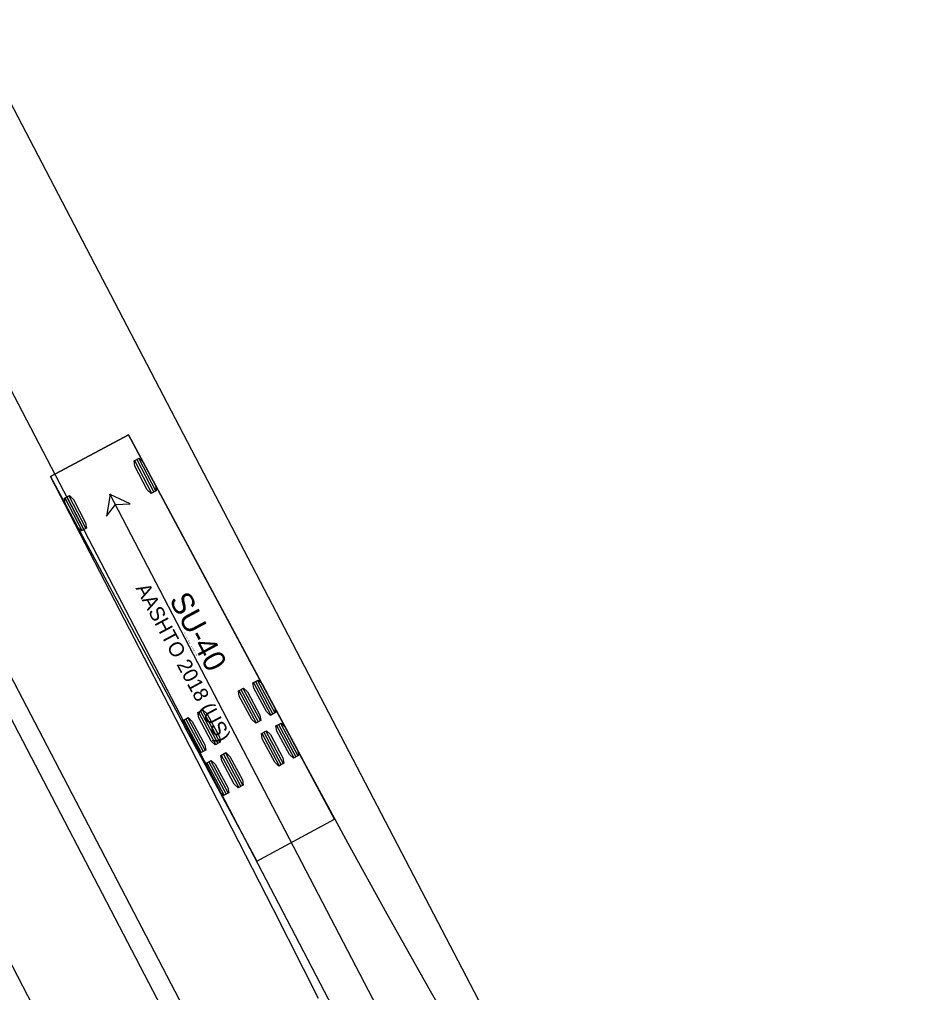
# Model space of a CAD drawing. Extents: x 2297881 to 2300600, y 559917 to 564426.
# Drawn here: x 2298908.1 to 2298989, y 562760.2 to 562848.3 of the extents above; entities that cross this region are included whole.
import ezdxf

# ---------------------------------------------------------------- set-up
doc = ezdxf.new("R2010")
doc.units = 0
for name, color, linetype in [('GE_X_Alignment', 7, 'Continuous'), ('PM_P_CL_Pass_Proh_Lt', 7, 'Continuous'), ('PM_P_Dotted_Line', 7, 'Continuous'), ('PM_P_Lane_Line', 7, 'Continuous'), ('SN_X_Public', 7, 'Continuous'), ('SV_X_Control_Cells_Found', 7, 'Continuous')]:
    doc.layers.add(name, color=color, linetype=linetype)

msp = doc.modelspace()

# ---------------------------------------------------------------- linework, layer by layer
at = {"layer": 'GE_X_Alignment'}
msp.add_line((2298386.276, 563783.359), (2299396.643, 561847.397), dxfattribs=at)
at = {"layer": 'PM_P_CL_Pass_Proh_Lt'}
msp.add_line((2298832.687, 562957.711), (2298969.176, 562696.185), dxfattribs=at)
at = {"layer": 'PM_P_Dotted_Line'}
msp.add_line((2298822.048, 562952.158), (2298958.537, 562690.633), dxfattribs=at)
at = {"layer": 'PM_P_Lane_Line'}
msp.add_line((2298843.325, 562963.263), (2299419.428, 561859.394), dxfattribs=at)
at = {"layer": 'SN_X_Public'}
for p, q in [((2298917.929, 562810.739), (2298910.88, 562806.957)), ((2298936.607, 562775.935), (2298917.929, 562810.739)), ((2298918.501, 562808.395), (2298920.042, 562805.439)), ((2298918.686, 562808.491), (2298920.226, 562805.535)), ((2298918.87, 562808.588), (2298920.411, 562805.632)), ((2298910.88, 562806.957), (2298929.558, 562772.152)), ((2298910.88, 562806.957), (2298910.88, 562806.957)), ((2298912.181, 562805.015), (2298913.722, 562802.059)), ((2298912.366, 562805.111), (2298913.907, 562802.156)), ((2298912.551, 562805.208), (2298914.092, 562802.252)), ((2298961.104, 562719.36), (2298916.296, 562805.323)), ((2298928.309, 562787.786), (2298929.885, 562784.849)), ((2298929.263, 562788.298), (2298930.839, 562785.361)), ((2298929.447, 562788.397), (2298931.023, 562785.459)), ((2298929.63, 562788.495), (2298931.207, 562785.558)), ((2298927.941, 562787.589), (2298929.518, 562784.652)), ((2298928.125, 562787.687), (2298929.701, 562784.75)), ((2298924.27, 562785.618), (2298925.846, 562782.681)), ((2298924.454, 562785.717), (2298926.03, 562782.78)), ((2298924.637, 562785.815), (2298926.213, 562782.878)), ((2298922.948, 562784.909), (2298924.525, 562781.972)), ((2298923.132, 562785.008), (2298924.708, 562782.071)), ((2298923.316, 562785.106), (2298924.892, 562782.169)), ((2298931.344, 562784.421), (2298932.92, 562781.484)), ((2298931.527, 562784.52), (2298933.104, 562781.582)), ((2298931.711, 562784.618), (2298933.287, 562781.681)), ((2298930.022, 562783.712), (2298931.598, 562780.775)), ((2298930.206, 562783.81), (2298931.782, 562780.873)), ((2298930.389, 562783.909), (2298931.965, 562780.972)), ((2298926.351, 562781.741), (2298927.927, 562778.804)), ((2298926.534, 562781.84), (2298928.11, 562778.903)), ((2298926.718, 562781.938), (2298928.294, 562779.001)), ((2298925.029, 562781.032), (2298926.605, 562778.095)), ((2298925.213, 562781.131), (2298926.789, 562778.194)), ((2298925.396, 562781.229), (2298926.972, 562778.292)), ((2298929.558, 562772.152), (2298936.607, 562775.935))]:
    msp.add_line(p, q, dxfattribs=at)
for points in [[(2298935.14, 562759.715), (2298931.065, 562767.761), (2298921.625, 562786.187), (2298910.88, 562806.957), (2298917.929, 562810.739), (2298934.006, 562780.793), (2298937.819, 562773.776), (2298941.353, 562767.365), (2298945.266, 562760.404), (2298948.756, 562754.351)], [(2298916.296, 562805.323), (2298915.95, 562803.354), (2298916.758, 562804.437), (2298918.109, 562804.479), (2298916.296, 562805.323)]]:
    msp.add_lwpolyline(points, dxfattribs=at)
for points in [[(2298918.455, 562808.371), (2298918.916, 562808.612), (2298919.271, 562808.27), (2298920.38, 562806.142), (2298920.457, 562805.656), (2298919.996, 562805.415), (2298919.641, 562805.757), (2298918.532, 562807.885)], [(2298912.135, 562804.991), (2298912.597, 562805.232), (2298912.951, 562804.89), (2298914.061, 562802.762), (2298914.137, 562802.276), (2298913.676, 562802.035), (2298913.322, 562802.377), (2298912.212, 562804.505)], [(2298916.296, 562805.323), (2298915.95, 562803.354), (2298916.758, 562804.437), (2298918.109, 562804.479)], [(2298927.896, 562787.564), (2298928.354, 562787.81), (2298928.713, 562787.473), (2298929.848, 562785.358), (2298929.93, 562784.873), (2298929.472, 562784.627), (2298929.113, 562784.964), (2298927.979, 562787.079)], [(2298929.218, 562788.274), (2298929.676, 562788.519), (2298930.035, 562788.182), (2298931.169, 562786.068), (2298931.252, 562785.582), (2298930.794, 562785.336), (2298930.435, 562785.674), (2298929.3, 562787.788)], [(2298924.225, 562785.594), (2298924.683, 562785.84), (2298925.041, 562785.503), (2298926.176, 562783.388), (2298926.259, 562782.903), (2298925.801, 562782.657), (2298925.442, 562782.994), (2298924.307, 562785.109)], [(2298922.903, 562784.885), (2298923.361, 562785.131), (2298923.72, 562784.793), (2298924.855, 562782.679), (2298924.937, 562782.193), (2298924.479, 562781.948), (2298924.12, 562782.285), (2298922.985, 562784.399)], [(2298931.298, 562784.397), (2298931.756, 562784.642), (2298932.115, 562784.305), (2298933.25, 562782.191), (2298933.333, 562781.705), (2298932.874, 562781.459), (2298932.516, 562781.797), (2298931.381, 562783.911)], [(2298929.977, 562783.687), (2298930.435, 562783.933), (2298930.793, 562783.596), (2298931.928, 562781.481), (2298932.011, 562780.996), (2298931.553, 562780.75), (2298931.194, 562781.087), (2298930.059, 562783.202)], [(2298926.305, 562781.717), (2298926.763, 562781.963), (2298927.122, 562781.626), (2298928.257, 562779.511), (2298928.34, 562779.026), (2298927.881, 562778.78), (2298927.523, 562779.117), (2298926.388, 562781.232)], [(2298924.983, 562781.008), (2298925.442, 562781.254), (2298925.8, 562780.917), (2298926.935, 562778.802), (2298927.018, 562778.316), (2298926.56, 562778.071), (2298926.201, 562778.408), (2298925.066, 562780.522)]]:
    msp.add_lwpolyline(points, close=True, dxfattribs=at)
msp.add_circle((2298916.296, 562805.323), 0.0417, dxfattribs=at)
at = {"layer": 'SV_X_Control_Cells_Found'}
msp.add_line((2298478.285, 563584.907), (2298947.899, 562685.08), dxfattribs=at)

# ---------------------------------------------------------------- texts
at = {"layer": 'SN_X_Public'}
for s, height, p in [('AASHTO 2018 (US)', 1.33333, (2298918.564, 562796.853)), ('SU-40', 2, (2298921.588, 562795.801)), ('(c) 2021 Transoft Solutions, Inc. All rights reserved.', 0.08, (2298922.938, 562792.863))]:
    msp.add_text(s, height=height, rotation=298.22031, dxfattribs=at).set_placement(p)

doc.saveas('drawing.dxf')
